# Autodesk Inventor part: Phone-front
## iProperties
Shininess: 64.0
Length Units: 11269
Angle Units: 11279
Time Units: 11290
Mass Units: 11283
Length Display Precision: 3
Angle Display Precision: 2
Compacted: True
Part Number: Phone-front
Document SubType Name: Modeling
Created: 2002-12
Designer: deepak
Density: 0.0
Volumn: 0.0
Area: 0.0
PropertySet Name: Model Information
Control State: 0
Master: False
Checked Out: False
Author: deepak
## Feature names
1. Loft1
2. Split1
3. Shell2
